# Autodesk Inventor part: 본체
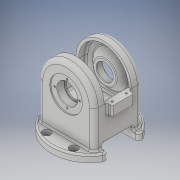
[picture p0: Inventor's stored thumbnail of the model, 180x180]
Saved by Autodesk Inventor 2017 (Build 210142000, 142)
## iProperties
Part Number: 본체
Material: 일반
Document SubType Name: Modeling
Designer: MRC
Density: 1 g/cm^3
Appearance: 기본값
Author: MRC
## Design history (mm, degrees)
sketch "스케치1"
  geometry: C1 r 71 at (0, 0); 1 further point
  constraints: 1 centre point, 1 coincident
  dimensions: "d0" = 142 diameter of C1
extrude "돌출1" new body sketch "스케치1" distance "d1" = 13; taper "d2" = 0 deg
sketch "스케치2"
  geometry: L1 (-71, 0)-(71, 0) reference; L2 (51, 81)-(51, 0); L3 (51, 0)-(-51, 0); L4 (-51, 0)-(-51, 81); A1 r 51 centre (0, 81) between (51, 81) and (-51, 81); 2 further points
  constraints: 6 end point, 2 point on circle, 2 tangent, 1 centre point, 1 midpoint, 1 parallel, 1 point on line, 1 vertical alignment
  dimensions: "d3" = 102 diameter of A1; "d4" = 81 distance of point (0, 0) A1.centre; "d5" = 102 distance of L2.end L3.end; "d6" = 81 distance of L3.end L4.end
extrude "돌출2" join sketch "스케치2" stored distance "d7" = 88; taper "d8" = 0 deg
sketch "스케치3"
  geometry: L1 (81, 20)-(61, 20); L2 (61, 20)-(61, -20); L3 (61, -20)-(81, -20); L4 (81, -20)-(81, 20); 2 further points
  constraints: 8 end point, 2 parallel, 1 horizontal, 1 horizontal alignment, 1 midpoint, 1 perpendicular
  dimensions: "d9" = 20 distance of L3.end L2.end; "d10" = 40 distance of L2.end L1.end; "d11" = 81 distance from line of point (0, 0) L4
extrude "돌출3" join sketch "스케치3" stored distance "d12" = 122; taper "d13" = 0 deg
sketch "스케치4"
  geometry: L1 (46, 81)-(46, 40); L2 (46, 40)-(-46, 40); L3 (-46, 40)-(-46, 81); A1 r 51 centre (0, 81) between (51, 81) and (-51, 81) reference; A2 r 46 centre (0, 81) between (46, 81) and (-46, 81); 1 further point
  constraints: 6 end point, 2 point on circle, 1 centre point, 1 parallel, 1 perpendicular, 1 tangent
  dimensions: "d14" = 40 distance from line of L2 point (0, 0); "d15" = 5 radial gap between concentric circles of A1 A2; "d16" = 92 distance of L1.end L2.end; "d17" = 41 distance of L1.start L1.end
extrude "돌출4" cut sketch "스케치4" stored distance "d18" = 78; taper "d19" = 0 deg
sketch "스케치5"
  geometry: L1 (127, 39)-(81, 39) reference; L2 (81, 39)-(40, 39) reference; L3 (114.5, 39)-(102.5, 27); L4 (102.5, 27)-(81, 27); L5 (81, 27)-(81, 39); L6 (81, 39)-(114.5, 39); 1 further point
  constraints: 8 end point, 1 collinear, 1 horizontal, 1 point on line
  dimensions: "d20" = 135 deg angle of L4 L3; "d22" = 67 diameter of L3.start L5; "d23" = 12 distance of L4.end L1.end; "d25" = 81 horizontal distance of point (0, 0) L4.end
revolve "회전1" sketch "스케치5" stored, may be unused: angle "d26" = 90 deg
sketch "스케치6"
  geometry: L1 (81, -39)-(81, 39) reference; L2 (154.956, 25)-(81, 25); L3 (81, 25)-(81, -25); L4 (81, -25)-(154.956, -25); L5 (154.956, -25)-(154.956, 25); 2 further points
  constraints: 8 end point, 2 parallel, 1 horizontal, 1 horizontal alignment, 1 midpoint, 1 perpendicular, 1 point on line
  dimensions: "d27" = 50 distance of L4.end L2.start; "d28" = 73.9558 distance of L2.start L2.end
extrude "돌출5" cut sketch "스케치6" stored distance "d29" = 78; taper "d30" = 0 deg
sketch "스케치7"
  geometry: C1 r 16 at (0, 81); A1 r 51 centre (0, 81) between (51, 81) and (-51, 81) reference; 1 further point
  constraints: 1 centre point, 1 coincident
  dimensions: "d31" = 32 diameter of C1
extrude "돌출6" cut sketch "스케치7" stored distance "d32" = 78; taper "d33" = 0 deg
sketch "스케치8"
  geometry: C1 r 16 at (0, 81) reference; C2 r 30 at (0, 81); 1 further point
  constraints: 1 centre point, 1 coincident
  dimensions: "d34" = 60 diameter of C2
extrude "돌출7" cut sketch "스케치8" distance "d35" = 2; taper "d36" = 0 deg
sketch "스케치9"
  geometry: C1 r 30 at (0, 0) reference; C2 r 18.5 at (0, 0); 1 further point
  constraints: 1 centre point, 1 coincident
  dimensions: "d37" = 37 diameter of C2
extrude "돌출8" cut sketch "스케치9" distance "d38" = 13; taper "d39" = 0 deg
sketch "스케치10"
  geometry: L1 (19, -28)-(-12.839, -28); L2 (-12.839, -28)-(-12.839, 28); L3 (-12.839, 28)-(19, 28); L4 (19, 28)-(19, -28); 2 further points
  constraints: 8 end point, 2 parallel, 1 horizontal, 1 horizontal alignment, 1 midpoint, 1 perpendicular
  dimensions: "d40" = 19 distance from line of L4 point (0, 0); "d41" = 56 distance of L1.end L2.end; "d42" = 31.83878 distance of L2.end L3.end
extrude "돌출9" cut sketch "스케치10" stored distance "d43" = 13; taper "d44" = 0 deg
sketch "스케치11"
  geometry: C1 r 30 at (0, 0); 1 further point
  constraints: 1 centre point, 1 coincident
  dimensions: "d45" = 60 diameter of C1
extrude "돌출10" cut sketch "스케치11" distance "d46" = 22; taper "d47" = 0 deg
sketch "스케치12"
  geometry: C1 r 14 at (0, 0); 1 further point
  constraints: 1 centre point, 1 coincident
  dimensions: "d48" = 28 diameter of C1
extrude "돌출11" cut sketch "스케치12" distance "d49" = 15; taper "d50" = 0 deg
sketch "스케치13"
  geometry: C1 r 11 at (0, 0); 1 further point
  constraints: 1 centre point, 1 coincident
  dimensions: "d51" = 22 diameter of C1
extrude "돌출12" cut sketch "스케치13" distance "d52" = 15; taper "d53" = 0 deg
sketch "스케치14"
  geometry: L1 (-25, 55)-(25, 55); L2 (25, 55)-(25, -55); L3 (25, -55)-(-25, -55); L4 (-25, -55)-(-25, 55); L5 (-25, 55)-(25, -55); L6 (25, 55)-(-25, -55); 5 further points
  constraints: 12 end point, 4 coincident, 2 midpoint, 2 parallel, 1 horizontal, 1 perpendicular
  dimensions: "d54" = 50 distance of L2.end L3.end; "d55" = 110 distance of L1.end L2.end
hole "구멍1" sketch "스케치14" at (25, 55), (25, -55), (-25, -55), (-25, 55) diameter "d56" = 9; stored, may be unused: countersink angle "d60" = 90 deg, drill point angle "d62" = 118 deg; dims "d57" = 6, "d58" = 15, "d59" = 8.8, "d61" = 8
sketch "스케치15"
  geometry: C1 r 30 at (0, 0) reference; A1 r 23 centre (0, 0) between (0, 23) and (23, 0); 3 further points
  constraints: 4 point on circle, 2 horizontal alignment, 2 vertical alignment, 1 centre point, 1 coincident
  dimensions: "d63" = 46 diameter of A1
hole "구멍2" sketch "스케치15" at (0, 23), (23, 0), (-23, 0), (0, -23) diameter "d64" = 3.242; stored, may be unused: countersink angle "d68" = 90 deg, drill point angle "d70" = 118 deg; dims "d65" = 8, "d66" = 15, "d67" = 8.8, "d69" = 10
sketch "스케치16"
  geometry: L1 (3, 33)-(-105, 33); L2 (-105, 33)-(-105, 7); L3 (-105, 7)-(3, 7); L4 (3, 7)-(3, 33); L5 (3, 33)-(-105, 7); L6 (-105, 33)-(3, 7); 5 further points
  constraints: 12 end point, 4 coincident, 2 midpoint, 2 parallel, 1 horizontal, 1 perpendicular
  dimensions: "d71" = 108 distance of L3.end L2.end; "d72" = 26 distance of L2.end L1.end
hole "구멍3" sketch "스케치16" at (3, 7), (3, 33), (-105, 33), (-105, 7) diameter "d73" = 3.242; stored, may be unused: countersink angle "d77" = 90 deg, drill point angle "d79" = 118 deg; dims "d74" = 8, "d75" = 15, "d76" = 8.8, "d78" = 10
sketch "스케치17"
  geometry: A1 r 23 centre (0, 0) between (0, -23) and (-23, 0); 3 further points
  constraints: 4 point on circle, 2 horizontal alignment, 2 vertical alignment, 1 centre point, 1 coincident
  dimensions: "d80" = 46 diameter of A1
hole "구멍4" sketch "스케치17" at (0, -23), (-23, 0), (23, 0), (0, 23) diameter "d81" = 3.242; stored, may be unused: countersink angle "d85" = 90 deg, drill point angle "d87" = 118 deg; dims "d82" = 8, "d83" = 15, "d84" = 8.8, "d86" = 10
sketch "스케치18"
  geometry: L1 (65.246, 0)-(65.246, 13) reference; L2 (-65.246, 13)-(65.246, 13) reference; L3 (-65.246, 13)-(-65.246, 0) reference; L4 (65.246, 0)-(-65.246, 0) reference; 3 further points
  constraints: 1 midpoint, 1 vertical alignment, 1 other
  dimensions: "d88" = 30 vertical distance of point (0, 30) L1.start
feature "엠보싱1" sketch "스케치18" dims "d0" = 142, "d89" = 0.5, "d90" = 0
fillet "모깎기1" dims "d91" = 6
fillet "모깎기2" dims "d92" = 8
fillet "모깎기3" dims "d93" = 0.3
fillet "모깎기4" dims "d94" = 3
fillet "모깎기5" dims "d95" = 3
fillet "모깎기6" dims "d96" = 3
fillet "모깎기7" dims "d97" = 3
fillet "모깎기8" dims "d98" = 3
fillet "모깎기9" dims "d99" = 3
fillet "모깎기10" dims "d100" = 3
fillet "모깎기11" dims "d101" = 3
chamfer "모따기1" distance "d102" = 1; stored, may be unused: second distance "d103" = 2, angle "d104" = 45 deg
node "솔리드1"
mirror "미러1"
mirror "미러2"
mirror "미러3"
node "투영된 루프1"
